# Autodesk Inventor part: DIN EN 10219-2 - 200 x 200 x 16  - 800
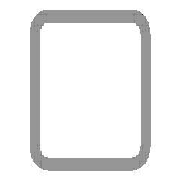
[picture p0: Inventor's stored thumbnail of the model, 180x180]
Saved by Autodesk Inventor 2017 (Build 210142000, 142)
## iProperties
Created: 2017-11
Part Number: DIN EN 10219-2 - 200 x 200 x 16  - 800
Material: Steel, Mild
Description: Cold formed welded structural hollow sections of non-alloy and fine grain structural steel
Document SubType Name: Modeling
Standard: DIN
Designer: iusti
Standard Revision: 2006-07
Standards Organization: DIN
Language: en-US
Size Designation: 200 x 200 x 16
Categories: <MemberInstance><Categories><Category DisplayName="Structural Shapes" InternalName="089c4875-fa83-4c05-b084-43b9cc11f5ed" Mnemonic="GRDR"><CategoryParameter Dis
Stock Number: 200 x 200 x 16
Mass: 67053.1 g
Surface Area: 10890.8 cm^2
Volume: 8541.79 cm^3
Density: 7.85 g/cm^3
Appearance: Semi-Polished
G_L: 800.000 mm
G_W: 200.000 mm
G_H: 200.000 mm
+6F84F5FA-068B-4035-A374-AD197C67666E+CUTDETAIL1: Cut
+D4A8A2DA-C34A-4EF5-ADA6-744FAFA5DC9C+CUTDETAIL2: Cut
IsCustomPart: 1
_CCFamilyMember: 103
_CCFamilyDisplayName: DIN EN 10219-2 (Square Hollow Section - Cold Formed) - Cold formed welded structural hollow sections of non-alloy and fine grain structural steel
_FrameMemberDoc: Frame Member File
_Version: 15.0.0
_GetPNFromCC: 1
Author: iusti
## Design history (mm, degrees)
node "Start plane"
node "End plane"
sketch "Sketch"
  geometry: L1 (-100, -52)-(-100, 52); L2 (-52, 100)-(52, 100); L3 (100, 52)-(100, -52); L4 (52, -100)-(-52, -100); L5 (-52, 84)-(52, 84); L6 (84, 52)-(84, -52); L7 (52, -84)-(-52, -84); L8 (-84, -52)-(-84, 52); L9 (0, 153.918)-(0, -153.918) reference; L10 (-153.918, 0)-(153.918, 0) reference; A1 r 48 centre (-52, -52) between (-100, -52) and (-52, -100); A2 r 48 centre (-52, 52) between (-52, 100) and (-100, 52); A3 r 48 centre (52, 52) between (100, 52) and (52, 100); A4 r 48 centre (52, -52) between (52, -100) and (100, -52); A5 r 32 centre (-52, 52) between (-52, 84) and (-84, 52); A6 r 32 centre (52, 52) between (84, 52) and (52, 84); A7 r 32 centre (52, -52) between (52, -84) and (84, -52); A8 r 32 centre (-52, -52) between (-84, -52) and (-52, -84)
  constraints: 16 end point, 16 point on circle, 8 centre point, 8 tangent, 4 parallel, 3 equal radius, 2 perpendicular, 7 other
  dimensions: "d7" = 48 radius of A1 (= G_IR); "d10" = 200 distance between parallel lines of L2 L4 (= G_H); "d11" = 200 distance between parallel lines of L1 L3 (= G_W); "d12" = 16 distance between parallel lines of L3 L6 (= G_T); "d15" = 100 distance between parallel lines of L2 L10 (= 0.5 x d10); "d16" = 100 distance between parallel lines of L9 L3 (= 0.5 x d11)
extrude "Body" new body sketch "Sketch" stored distance "d3" = 800 (= G_L); taper "d4" = 0 deg
node "Driven Length"
  sketch "Sketch3"
    geometry: L1 (0, 0)-(10, 0) reference
    constraints: 2 end point, 1 horizontal
  workplane "Work Plane3"
  sketch "Sketch4"
    geometry: L1 (-2, 100)-(12, 100) reference; L2 (-2, 900)-(12, 900) reference
    dimensions: "d18" = 800 distance between parallel lines of L1 L2 (derived)
workplane "Work Plane4"
split "Split1"
workplane "Work Plane5"
split "Split2"
body "Solid1"
other parameters: "G_W" = 200 [user parameter; used in 1 equation term], "G_H" = 200 [user parameter; used in 1 equation term], "G_T" = 16 [user parameter; used in 1 equation term], "G_IR" = 48 [user parameter; used in 1 equation term], "G_L" = 800 (= d18) [user parameter; used in 1 equation term], "d17" = 90 deg
